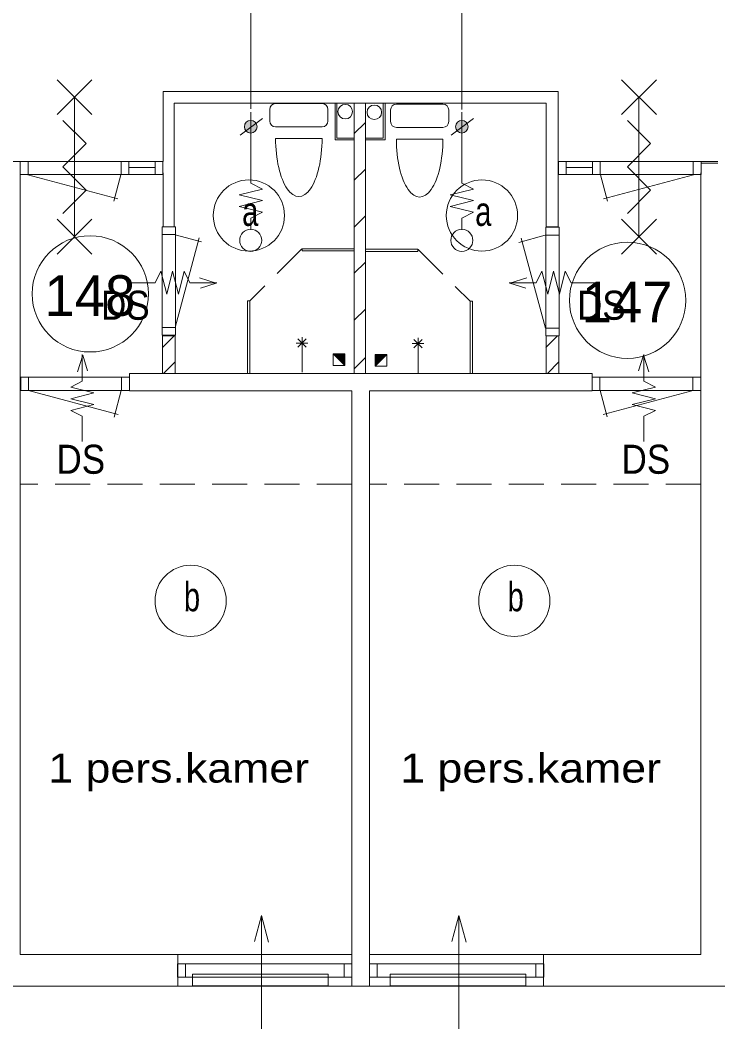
# Model space of a CAD drawing. Extents: x 295824 to 414724, y 24924 to 109024.
# Drawn here: x 320086 to 326087, y 61928 to 70606 of the extents above; entities that cross this region are included whole.
import ezdxf
from ezdxf.enums import TextEntityAlignment as Align

# ---------------------------------------------------------------- set-up
doc = ezdxf.new("R2010")
doc.units = 0
doc.header["$LTSCALE"] = 100
doc.linetypes.add('MEDIUM_DASHED', pattern=[4.5, 3, -1.5])
for name, color, linetype, lineweight in [('1', 7, 'Continuous', 13), ('16', 7, 'Continuous', 13), ('24', 7, 'Continuous', 13), ('61', 7, 'Continuous', 13)]:
    doc.layers.add(name, color=color, linetype=linetype, lineweight=lineweight)

msp = doc.modelspace()

# ---------------------------------------------------------------- hatches: boundary and pattern name
at = {"layer": '24'}
for points in [[(322123.6, 69688.9, 1), (322015, 69688.9, 1)], [(323939.2, 69688.9, 1), (323830.6, 69688.9, 1)]]:
    msp.add_hatch(color=256, dxfattribs=at).paths.add_polyline_path(points)
at = {"layer": '61'}
for points in [[(322777.9, 67734.4), (322877.9, 67634.4), (322877.9, 67734.4)], [(323240.3, 67729), (323140.3, 67629), (323140.3, 67729)]]:
    msp.add_hatch(color=256, dxfattribs=at).paths.add_polyline_path(points)

# ---------------------------------------------------------------- linework, layer by layer
at = {"layer": '1'}
for p, q in [((322069.3, 69843.4), (322069.3, 70726.3)), ((323884.9, 69838.4), (323884.9, 70726.3))]:
    msp.add_line(p, q, dxfattribs=at)
at = {"layer": '16'}
for p, q in [((321396.7, 68447.5), (321346.7, 68247.5)), ((324674.2, 68447.5), (324724.2, 68247.5)), ((320520.3, 67349.3), (320720.3, 67299.3)), ((325550.6, 67349.3), (325350.6, 67299.3))]:
    msp.add_line(p, q, dxfattribs=at)
at = {"layer": '24'}
for p, q in [((322069.3, 69253.4), (322069.3, 69814.2)), ((323884.9, 69253.4), (323884.9, 69815.7)), ((321977.7, 69618), (322169.3, 69759.7)), ((323793.3, 69618), (323984.8, 69759.7)), ((321772.1, 68344.1), (321627.9, 68389.2)), ((324298.7, 68344.1), (324442.9, 68389.2)), ((321636.3, 68301.7), (321772.1, 68344.1)), ((324434.5, 68301.7), (324298.7, 68344.1)), ((320623.7, 67724.8), (320578.6, 67580.6)), ((320666.1, 67588.9), (320623.7, 67724.8)), ((325404.8, 67588.9), (325447.2, 67724.8)), ((325447.2, 67724.8), (325492.2, 67580.6)), ((322161, 62903.3), (322101.4, 62680.9)), ((323859.9, 62903.3), (323800.3, 62680.9))]:
    msp.add_line(p, q, dxfattribs=at)
for points in [[(322069.3, 68803.4), (322069.3, 68903.4), (322169.3, 68953.4), (321969.3, 69003.4), (322169.3, 69053.4), (321969.3, 69103.4), (322169.3, 69153.4), (322069.3, 69203.4), (322069.3, 69253.4)], [(323884.9, 68803.4), (323884.9, 68903.4), (323984.9, 68953.4), (323784.9, 69003.4), (323984.9, 69053.4), (323784.9, 69103.4), (323984.9, 69153.4), (323884.9, 69203.4), (323884.9, 69253.4)], [(321346.7, 68247.5), (321296.7, 68447.5), (321246.7, 68347.5), (321027.9, 68347.5)], [(321777.9, 68347.5), (321546.7, 68347.5), (321496.7, 68447.5), (321446.7, 68247.5), (321396.7, 68447.5)], [(324292.9, 68347.5), (324524.2, 68347.5), (324574.2, 68447.5), (324624.2, 68247.5), (324674.2, 68447.5)], [(324724.2, 68247.5), (324774.2, 68447.5), (324824.2, 68347.5), (325042.9, 68347.5)], [(320620.3, 67730.6), (320620.3, 67499.3), (320520.3, 67449.3), (320720.3, 67399.3), (320520.3, 67349.3)], [(325450.6, 67730.6), (325450.6, 67499.3), (325550.6, 67449.3), (325350.6, 67399.3), (325550.6, 67349.3)], [(320720.3, 67299.3), (320520.3, 67249.3), (320620.3, 67199.3), (320620.3, 66980.6)], [(325350.6, 67299.3), (325550.6, 67249.3), (325450.6, 67199.3), (325450.6, 66980.6)], [(322161, 61928.3), (322161, 62903.3), (322222.6, 62673.1)], [(323859.9, 61928.3), (323859.9, 62903.3), (323921.6, 62673.1)]]:
    msp.add_lwpolyline(points, dxfattribs=at)
for points in [[(321569.6, 62399.1), (322735.6, 62399.1), (322735.6, 62299.1), (321569.6, 62299.1)], [(323268.6, 62399.1), (324434.5, 62399.1), (324434.5, 62299.1), (323268.6, 62299.1)]]:
    msp.add_lwpolyline(points, close=True, dxfattribs=at)
for centre, radius in [((322069.3, 69688.9), 54.3), ((323884.9, 69688.9), 54.3), ((322069.3, 68711.8), 95), ((323884.9, 68711.8), 95)]:
    msp.add_circle(centre, radius, dxfattribs=at)
at = {"layer": '61'}
for p, q in [((320403, 69794.2), (320703, 70094.2)), ((320703, 69794.2), (320403, 70094.2)), ((325258.8, 69794.2), (325558.8, 70094.2)), ((325558.8, 69794.2), (325258.8, 70094.2)), ((320553, 69944.2), (320553, 68744.2)), ((325408.8, 69944.2), (325408.8, 68744.2)), ((321409.7, 68829.5), (321409.7, 69891.5)), ((322282.9, 69888.5), (322682.9, 69888.5)), ((322809.7, 69591.5), (322809.7, 69891.5)), ((322959.7, 67566.5), (322959.7, 69891.5)), ((323056, 67566.5), (323056, 69891.5)), ((323209.7, 69891), (323209.7, 69591)), ((323224.7, 69891), (323224.7, 69576)), ((323322.2, 69883.6), (323722.2, 69883.6)), ((322232.9, 69738.5), (322232.9, 69838.5)), ((322732.9, 69838.5), (322732.9, 69738.5)), ((323272.2, 69733.6), (323272.2, 69833.6)), ((323772.2, 69833.6), (323772.2, 69733.6)), ((322682.9, 69688.5), (322282.9, 69688.5)), ((323055.4, 69725.6), (322959.6, 69629.8)), ((323722.2, 69683.6), (323322.2, 69683.6)), ((322282.9, 69588.5), (322682.9, 69588.5)), ((322959.7, 69591.5), (322809.7, 69591.5)), ((323209.7, 69591), (323059.7, 69591)), ((323224.7, 69576), (323059.7, 69576)), ((323322.2, 69583.6), (323722.2, 69583.6)), ((319949.3, 69391.4), (320090.5, 69391.4)), ((320153.5, 69391.4), (320153.5, 69277.4)), ((320953.5, 69391.4), (320953.5, 69277.4)), ((321020.5, 69391.4), (321020.5, 69277.4)), ((321246.5, 69337.3), (321020.5, 69337.3)), ((321246.5, 69391.4), (321246.5, 69277.4)), ((324714.9, 68828), (324714.9, 69393.9)), ((324783.1, 69391.4), (324783.1, 69277.4)), ((324783.1, 69337.4), (325009.1, 69337.4)), ((325009.1, 69391.4), (325009.1, 69277.4)), ((325076.1, 69391.4), (325076.1, 69277.4)), ((325876.1, 69391.4), (325876.1, 69277.4)), ((325944.5, 69376.4), (326085.7, 69376.4)), ((325945.2, 69391.4), (326086.3, 69391.4)), ((320087, 69291.5), (320087, 62566.5)), ((320152.7, 69276.8), (320925.4, 69069.7)), ((320951.1, 69276.2), (320890.3, 69049.3)), ((321314.9, 68829.5), (321314.9, 69291.5)), ((323055.4, 69324.7), (322959.6, 69228.9)), ((325078.4, 69276.2), (325139.2, 69049.3)), ((325876.9, 69276.8), (325104.1, 69069.8)), ((325940.1, 69291.5), (325940.1, 62566.5)), ((323055.4, 68921.3), (322959.6, 68825.5)), ((320403, 68594.2), (320703, 68894.2)), ((320703, 68594.2), (320403, 68894.2)), ((321307.4, 67894.7), (321307.4, 68828.7)), ((321409.7, 68829.5), (321314.9, 68829.5)), ((324714.9, 68828), (324609.7, 68828)), ((324720.9, 67892), (324720.9, 68824.4)), ((325258.8, 68594.2), (325558.8, 68894.2)), ((325558.8, 68594.2), (325258.8, 68894.2)), ((321307.4, 68761.7), (321421.4, 68761.7)), ((321419.5, 67960.9), (321626.5, 68733.6)), ((321420.1, 68759.3), (321646.9, 68698.5)), ((324603, 68755.1), (324376.2, 68694.3)), ((324603.7, 67956.6), (324396.6, 68729.4)), ((324720.9, 68757.4), (324606.9, 68757.4)), ((322960.8, 68640.1), (322511.3, 68640.1)), ((322511.3, 68640.1), (322511.3, 68622.1)), ((322960.4, 68622.1), (322511.3, 68622.1)), ((323057.5, 68634.8), (323506.9, 68634.8)), ((323057.8, 68616.8), (323506.9, 68616.8)), ((323506.9, 68634.8), (323506.9, 68616.8)), ((323055.4, 68525.3), (322959.6, 68429.5)), ((322060.4, 67572.1), (322060.4, 68192.6)), ((323055.4, 68120.7), (322959.6, 68024.9)), ((323957.8, 67566.7), (323957.8, 68187.2)), ((321307.4, 67961.7), (321421.4, 67961.7)), ((324720.9, 67957.4), (324606.9, 67957.4)), ((321420.8, 67894.7), (321306.8, 67894.7)), ((321420.1, 67891.1), (321310.1, 67891.1)), ((321310.1, 67891.1), (321310.1, 67567.1)), ((321409.8, 67889.9), (321310.1, 67790.2)), ((321420.1, 67891.1), (321420.1, 67567.1)), ((322545.6, 67793.2), (322474.9, 67863.9)), ((322545.6, 67863.9), (322474.9, 67793.2)), ((322510.3, 67778.6), (322510.3, 67878.6)), ((323508, 67773.2), (323508, 67873.2)), ((324708.2, 67889.9), (324608.5, 67790.2)), ((324719.1, 67891.1), (324609.1, 67891.1)), ((324609.1, 67891.1), (324609.1, 67567.1)), ((324719.1, 67891.1), (324719.1, 67567.1)), ((322560.3, 67828.6), (322460.3, 67828.6)), ((322510.3, 67778.6), (322510.3, 67578.6)), ((323458, 67823.2), (323558, 67823.2)), ((323472.6, 67787.9), (323543.3, 67858.6)), ((323472.6, 67858.6), (323543.3, 67787.9)), ((323055.4, 67702.6), (322959.6, 67606.8)), ((323508, 67773.2), (323508, 67573.2)), ((321418.4, 67667.3), (321318.7, 67567.6)), ((324720.5, 67667.3), (324620.8, 67567.6)), ((320158, 67534), (320158, 67420)), ((320958, 67534), (320958, 67420)), ((321025, 67534), (321025, 67420)), ((321420.1, 67567.1), (321310.1, 67567.1)), ((324719.1, 67567.1), (324609.1, 67567.1)), ((325005.7, 67535.1), (325005.7, 67421.1)), ((325072.7, 67535.1), (325072.7, 67421.1)), ((325872.7, 67535.1), (325872.7, 67421.1)), ((320157.3, 67419.4), (320930, 67212.3)), ((320955.7, 67418.7), (320894.9, 67191.9)), ((322940.1, 62296.5), (322940.1, 67416.5)), ((323090.1, 62296.5), (323090.1, 67416.5)), ((325075, 67419.8), (325135.8, 67193)), ((325873.5, 67420.4), (325100.7, 67213.4)), ((320087, 62566.5), (322940.1, 62566.5)), ((321440.7, 62295.3), (321440.7, 62565.3)), ((321507.4, 62373.6), (321507.4, 62487.5)), ((322872.5, 62373), (322872.5, 62487)), ((325940.1, 62566.5), (323090.1, 62566.5)), ((323156, 62373.9), (323156, 62487.9)), ((324520.3, 62373.6), (324520.3, 62487.3)), ((324588.7, 62295.3), (324588.7, 62565.5)), ((326233, 62296.5), (307806, 62296.5))]:
    msp.add_line(p, q, dxfattribs=at)
at = {"layer": '61', "linetype": 'MEDIUM_DASHED'}
for p, q in [((322509.2, 68639.6), (322062.4, 68192.8)), ((323509, 68634.3), (323955.9, 68187.4)), ((322937.9, 66613.1), (320090.8, 66613.1)), ((325940.2, 66613.1), (323091.2, 66613.1)), ((325835.9, 66613.1), (325939.1, 66613.1))]:
    msp.add_line(p, q, dxfattribs=at)
at = {"layer": '61'}
for points in [[(324714.9, 69391.5), (324714.9, 69991.5), (321314.9, 69991.5), (321314.9, 69391.5)], [(324609.7, 68828), (324609.7, 69891.5), (321409.7, 69891.5)], [(322959.7, 69576.5), (322794.7, 69576.5), (322794.7, 69891.5)], [(320453, 69744.2), (320653, 69544.2), (320453, 69344.2), (320653, 69144.2), (320453, 68944.2)], [(325308.8, 69744.2), (325508.8, 69544.2), (325308.8, 69344.2), (325508.8, 69144.2), (325308.8, 68944.2)], [(322042.4, 67572.1), (322042.4, 68192.6), (322060.4, 68192.6)], [(323975.8, 67566.7), (323975.8, 68187.2), (323957.8, 68187.2)], [(322877.9, 67634.4), (322877.9, 67734.4), (322777.9, 67734.4)], [(323140.3, 67629), (323140.3, 67729), (323240.3, 67729)], [(320091, 67534), (320091, 67420), (321025, 67420)], [(321025, 67534), (320091, 67534), (320091, 67420)], [(323089.9, 67416.5), (325004.9, 67416.5), (325004.9, 67566.5), (321025.5, 67566.5)], [(322939.9, 67416.5), (321025.5, 67416.5), (321025.5, 67566.5)], [(325939.7, 67535.1), (325939.7, 67421.1), (325005.7, 67421.1)], [(325005.7, 67535.1), (325939.7, 67535.1), (325939.7, 67421.1)]]:
    msp.add_lwpolyline(points, dxfattribs=at)
for points in [[(321313.5, 69391.4), (321313.5, 69277.4), (320086.5, 69277.4), (320086.5, 69391.4)], [(321313.5, 69391.4), (321313.5, 69277.4), (320086.5, 69277.4), (320086.5, 69391.4)], [(325943.1, 69391.4), (325943.1, 69277.4), (324716.7, 69277.4), (324716.7, 69391.4)], [(325943.1, 69391.4), (325943.1, 69277.4), (324716.7, 69277.4), (324716.7, 69391.4)], [(321307.4, 67894.7), (321307.4, 68828.7), (321421.4, 68828.7), (321421.4, 67894.7)], [(324720.9, 68825.4), (324606.9, 68825.4), (324606.9, 67891.4), (324720.9, 67891.4)], [(322877.9, 67634.4), (322777.9, 67634.4), (322777.9, 67734.4)], [(322777.9, 67734.4), (322877.9, 67634.4), (322877.9, 67734.4)], [(323140.3, 67629), (323240.3, 67629), (323240.3, 67729)], [(323240.3, 67729), (323140.3, 67629), (323140.3, 67729)], [(321440.6, 62373.5), (321440.6, 62487.5), (322939.3, 62487.5), (322939.3, 62373.5)], [(323089.6, 62373.6), (323089.6, 62487.6), (324589, 62487.6), (324589, 62373.6)]]:
    msp.add_lwpolyline(points, close=True, dxfattribs=at)
for centre, radius in [((322882.2, 69819.1), 62.5), ((323132.2, 69813.5), 62.5), ((322053.3, 68925.6), 306.3), ((324057.9, 68925.6), 306.3), ((320688.9, 68251.4), 500), ((325310.5, 68195.7), 500), ((321552.2, 65610.1), 306.3), ((324336.3, 65610.1), 306.3)]:
    msp.add_circle(centre, radius, dxfattribs=at)
for centre, start, end in [((322282.9, 69838.5), 90, 180), ((322682.9, 69838.5), 0, 90), ((323322.2, 69833.6), 90, 180), ((323722.2, 69833.6), 0, 90), ((322282.9, 69738.5), 180, 270), ((322682.9, 69738.5), 270, 0), ((323322.2, 69733.6), 180, 270), ((323722.2, 69733.6), 270, 0)]:
    msp.add_arc(centre, 50, start, end, dxfattribs=at)
for centre in [(322482.9, 69588.5), (323522.2, 69583.6)]:
    msp.add_ellipse(centre, major_axis=(0, -500), ratio=0.4, start_param=4.712389, end_param=7.853982, dxfattribs=at)

# ---------------------------------------------------------------- texts
at = {"layer": '24', "width": 0.9}
for p in [(320781.5, 68028.5), (324875.9, 68028.5), (320398.4, 66703.6), (325259, 66703.6)]:
    msp.add_text('DS', height=250, dxfattribs=at).set_placement(p)
at = {"layer": '61'}
for s, width, p in [('a', 0.75, (321995.3, 68836.4)), ('a', 0.75, (323999.9, 68836.4)), ('b', 0.75, (321494.2, 65520.9)), ('b', 0.75, (324278.3, 65520.9)), ('1 pers.kamer', 1.15, (320327.6, 64046.9)), ('1 pers.kamer', 1.15, (323354.8, 64046.9))]:
    msp.add_text(s, height=250, dxfattribs=dict(at, width=width)).set_placement(p)
for s, p in [('148', (320686, 68061.6)), ('147', (325306.2, 68005.8))]:
    msp.add_text(s, height=350, dxfattribs=at).set_placement(p, align=Align.CENTER)

doc.saveas('drawing.dxf')
